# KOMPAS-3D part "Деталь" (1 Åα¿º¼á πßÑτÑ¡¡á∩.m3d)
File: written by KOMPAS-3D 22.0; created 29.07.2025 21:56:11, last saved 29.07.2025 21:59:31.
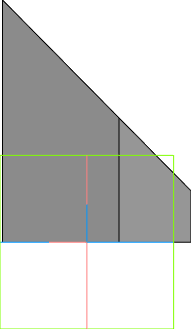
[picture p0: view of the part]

Document properties: Автор: user; Полное имя файла: G:\07 29 вторник\2025 НГ Лаб работы\Лаб 1 Сечение призмы\Сечение призмы Сплошная.m3d

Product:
- Part/product: Деталь
    Масса: 0.759578

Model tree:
1. Эскиз:1
2. Элемент выдавливания:1
     Расстояние 1 = 70
3. Эскиз:2  (with: Элемент выдавливания:1)
4. Элемент выдавливания:2
     Расстояние 1 = 28.5317; Расстояние 2 = 28.5317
